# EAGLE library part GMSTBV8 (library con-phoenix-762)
PHOENIX
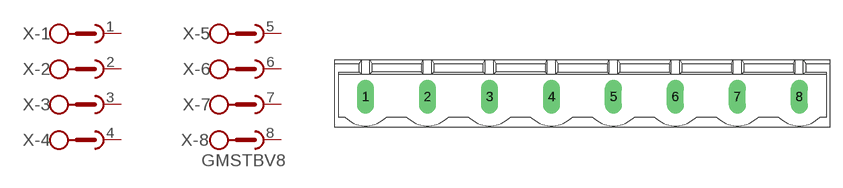
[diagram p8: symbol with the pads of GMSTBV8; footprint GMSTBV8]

Designator prefix X; gates -1=SKB -2=SKB -3=SKB -4=SKB -5=SKB -6=SKB -7=SKB -8=SKBV

## GMSTBV8 (MPN: GMSTBVA2,5/8-G-7,62; OC_FARNELL: 1793085; OC_NEWARK: 69R9525)  [GMSTBV8]
1  -1:1  pas
2  -2:1  pas
3  -3:1  pas
4  -4:1  pas
5  -5:1  pas
6  -6:1  pas
7  -7:1  pas
8  -8:1  pas

## Footprint GMSTBV8 (pad centres in mm)
PHOENIX
drill 1.397 long: 1 -26.67,0; 2 -19.05,0; 3 -11.43,0; 4 -3.81,0; 5 3.81,0; 6 11.43,0; 7 19.05,0; 8 26.67,0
